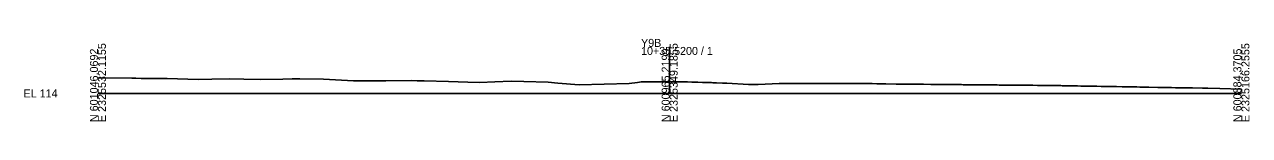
# Model space of a CAD drawing. Extents: x -26 to 3203, y 990 to 2017.
# Drawn here: x 2774.3 to 3202.8, y 990.3 to 1019 of the extents above; entities that cross this region are included whole.
import ezdxf

# ---------------------------------------------------------------- set-up
doc = ezdxf.new("R2010")
doc.units = 0
for name, color, linetype in [('Exist CMT Pavement', 7, 'Continuous'), ('Exist Cross Section Cell', 7, 'Continuous'), ('Exist XS Center Line Elevation Label', 7, 'Continuous'), ('Exist XS Ground Line', 7, 'Continuous'), ('Prop XS Earthwork Shape', 7, 'Continuous')]:
    doc.layers.add(name, color=color, linetype=linetype)

msp = doc.modelspace()

# ---------------------------------------------------------------- linework, layer by layer
at = {"layer": 'Exist CMT Pavement'}
msp.add_lwpolyline([(3000, 1004.04), (3000, 1004.14), (3000.1, 1004.14), (3000.1, 1004.04)], dxfattribs=at)
at = {"layer": 'Exist Cross Section Cell'}
for p, q in [((3000, 1000), (3000, 1016.18)), ((2800, 1000), (3000, 1000)), ((3000, 1000), (3200, 1000))]:
    msp.add_line(p, q, dxfattribs=at)
at = {"layer": 'Exist XS Ground Line'}
msp.add_lwpolyline([(2800, 1005.31), (2802.35, 1005.39), (2811.82, 1005.28), (2813.29, 1005.27), (2815.14, 1005.24), (2824.22, 1005.16), (2831.42, 1004.95), (2835.16, 1004.89), (2839.88, 1004.94), (2846.09, 1005.06), (2851.01, 1004.98), (2857.03, 1004.89), (2864.62, 1004.99), (2867.96, 1005.03), (2870.61, 1005.06), (2878.9, 1004.98), (2889.36, 1004.4), (2889.83, 1004.37), (2890.2, 1004.37), (2900.76, 1004.4), (2909.8, 1004.44), (2911.7, 1004.43), (2912.44, 1004.43), (2914.1, 1004.35), (2922.63, 1004.15), (2929.39, 1003.87), (2933.57, 1003.84), (2938.84, 1003.99), (2944.5, 1004.2), (2948.99, 1004.12), (2957.46, 1003.96), (2960.83, 1003.57), (2968.39, 1003.03), (2985.82, 1003.41), (2988.75, 1003.8), (2990.12, 1004.05), (2991.44, 1004.05), (2992, 1004.05), (2992.73, 1004.05), (2995.19, 1004.05), (2995.86, 1004.05), (2997.85, 1004.05), (2998.98, 1004.05), (2999.36, 1004.05), (3000, 1004.04), (3002.1, 1004.02), (3002.72, 1004.01), (3003.53, 1004.01), (3004.5, 1004), (3005.23, 1003.99), (3006.29, 1003.97), (3007.7, 1003.94), (3008.35, 1003.93), (3009.86, 1003.88), (3011.48, 1003.83), (3011.87, 1003.82), (3014.6, 1003.74), (3015.08, 1003.72), (3016.39, 1003.69), (3018.54, 1003.61), (3019.52, 1003.57), (3019.96, 1003.56), (3027.62, 1003.07), (3031.01, 1003.05), (3038.25, 1003.43), (3042.72, 1003.47), (3043.31, 1003.47), (3044.14, 1003.47), (3045.65, 1003.46), (3049.66, 1003.44), (3050.23, 1003.45), (3052.08, 1003.46), (3053.57, 1003.48), (3055.21, 1003.49), (3056.29, 1003.49), (3057.74, 1003.49), (3058.33, 1003.49), (3059.86, 1003.5), (3061.91, 1003.49), (3063.44, 1003.49), (3064.58, 1003.48), (3066.08, 1003.46), (3067.7, 1003.44), (3068.79, 1003.43), (3070.25, 1003.41), (3070.82, 1003.4), (3072.53, 1003.37), (3073.95, 1003.35), (3074.42, 1003.34), (3075.62, 1003.31), (3079.27, 1003.26), (3082.09, 1003.23), (3082.76, 1003.22), (3083.22, 1003.22), (3084.98, 1003.2), (3086.63, 1003.18), (3086.93, 1003.18), (3088.77, 1003.17), (3091.4, 1003.15), (3093.65, 1003.13), (3095.27, 1003.11), (3095.81, 1003.11), (3097.42, 1003.09), (3098.63, 1003.07), (3099.05, 1003.07), (3099.44, 1003.06), (3100.94, 1003.05), (3102.06, 1003.04), (3102.72, 1003.03), (3103.61, 1003.02), (3104.51, 1003.01), (3105.18, 1003.01), (3106.3, 1003), (3108.31, 1002.98), (3109.87, 1002.97), (3111.43, 1002.96), (3111.95, 1002.95), (3113.44, 1002.94), (3114.55, 1002.93), (3115.23, 1002.92), (3116.12, 1002.92), (3117.68, 1002.9), (3118.8, 1002.89), (3120.8, 1002.87), (3122.37, 1002.85), (3123.92, 1002.84), (3124.46, 1002.84), (3125.94, 1002.82), (3127.05, 1002.81), (3128.63, 1002.79), (3129.72, 1002.78), (3130.87, 1002.76), (3132.15, 1002.75), (3132.96, 1002.76), (3133.97, 1002.74), (3134.81, 1002.72), (3135.56, 1002.72), (3136.83, 1002.7), (3137.33, 1002.69), (3138.26, 1002.67), (3139.9, 1002.64), (3141.14, 1002.62), (3142.67, 1002.59), (3143.8, 1002.57), (3145.31, 1002.54), (3145.79, 1002.53), (3147.21, 1002.51), (3149.16, 1002.47), (3149.48, 1002.47), (3150.94, 1002.45), (3152.04, 1002.43), (3153.65, 1002.4), (3155.16, 1002.38), (3156.3, 1002.36), (3158.28, 1002.34), (3159.66, 1002.31), (3161.41, 1002.27), (3161.99, 1002.26), (3163.44, 1002.23), (3164.53, 1002.2), (3165.23, 1002.19), (3166.16, 1002.18), (3167.65, 1002.16), (3170.78, 1002.09), (3172.1, 1002.07), (3173.9, 1002.05), (3174.5, 1002.04), (3175.6, 1002.02), (3176.97, 1001.99), (3177.57, 1001.98), (3178.5, 1001.96), (3179.82, 1001.95), (3181.9, 1001.92), (3182.88, 1001.9), (3186.37, 1001.85), (3188.22, 1001.8), (3192.45, 1001.65), (3200, 1001.48)], dxfattribs=at)
at = {"layer": 'Prop XS Earthwork Shape'}
msp.add_lwpolyline([(3000, 1004.04), (3000.1, 1004.04), (3000.1, 1004.14), (3000, 1004.14)], close=True, dxfattribs=at)

# ---------------------------------------------------------------- texts
at = {"layer": 'Exist Cross Section Cell'}
for s, p in [('E 2325532.1155', (2802.8, 990)), ('E 2325349.1855', (3002.8, 990)), ('E 2325166.2555', (3202.8, 990)), ('N 601046.0692', (2800, 990)), ('N 600965.2199', (3000, 990)), ('N 600884.3705', (3200, 990))]:
    msp.add_text(s, height=2.8, rotation=90, dxfattribs=at).set_placement(p)
for s, p in [('Y9B', (2990, 1016.18)), ('10+35.5200 / 1', (2990, 1013.38)), ('EL 114', (2774, 998.6))]:
    msp.add_text(s, height=2.8, dxfattribs=at).set_placement(p)
at = {"layer": 'Exist XS Center Line Elevation Label'}
msp.add_text('118.04', height=0.2, dxfattribs=at).set_placement((2999.66, 1002.04))

doc.saveas('drawing.dxf')
